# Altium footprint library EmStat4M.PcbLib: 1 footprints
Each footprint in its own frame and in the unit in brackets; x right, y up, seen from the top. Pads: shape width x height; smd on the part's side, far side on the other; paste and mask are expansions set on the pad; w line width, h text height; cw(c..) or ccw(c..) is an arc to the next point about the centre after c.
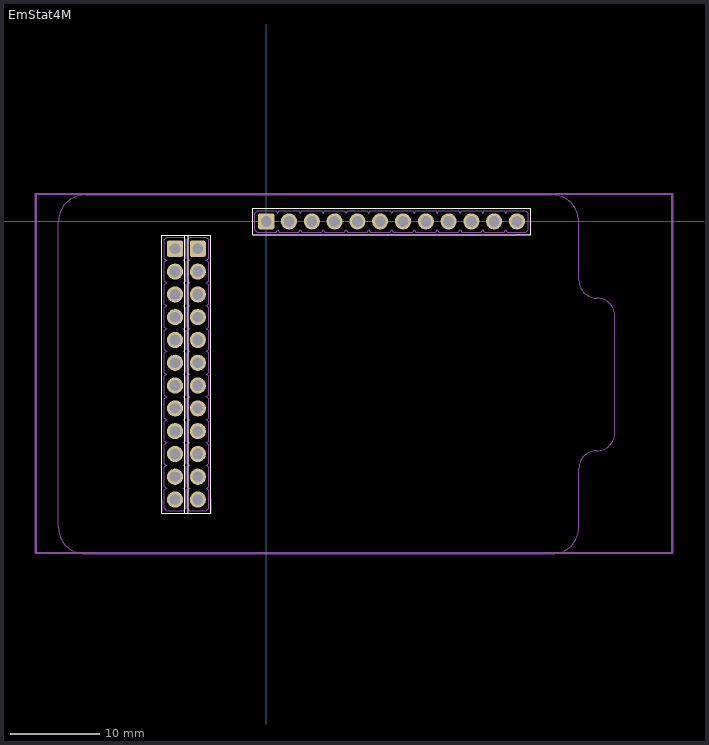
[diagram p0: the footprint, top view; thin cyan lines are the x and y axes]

## EmStat4M [mm] "EmStat 4 Module"
pads (36):
  rrect25% 1.8x1.8 hole 1.2: Con1-1(0,0) Con2-1(-10.16,-3.048) Con3-1(-7.62,-3.048)
  round 1.8 hole 1.2: Con1-2(2.54,0) Con1-3(5.08,0) Con1-4(7.62,0) Con1-5(10.16,0) Con1-6(12.7,0) Con1-7(15.24,0) Con1-8(17.78,0) Con1-9(20.32,0) Con1-10(22.86,0) Con1-11(25.4,0) Con1-12(27.94,0) Con2-2(-10.16,-5.588) Con2-3(-10.16,-8.128) Con2-4(-10.16,-10.668) Con2-5(-10.16,-13.208) Con2-6(-10.16,-15.748) Con2-7(-10.16,-18.288) Con2-8(-10.16,-20.828) Con2-9(-10.16,-23.368) Con2-10(-10.16,-25.908) Con2-11(-10.16,-28.448) Con2-12(-10.16,-30.988) Con3-2(-7.62,-5.588) Con3-3(-7.62,-8.128) Con3-4(-7.62,-10.668) Con3-5(-7.62,-13.208) Con3-6(-7.62,-15.748) Con3-7(-7.62,-18.288) Con3-8(-7.62,-20.828) Con3-9(-7.62,-23.368) Con3-10(-7.62,-25.908) Con3-11(-7.62,-28.448) Con3-12(-7.62,-30.988)
Top Overlay:
  lines w0.1: -11.62,-1.528 -11.62,-3.057 -11.62,-30.997 -11.62,-32.508 -10.15,-32.508 -8.708,-32.508 ; -11.612,-1.528 -10.17,-1.528 -8.7,-1.528 -8.7,-3.039 -8.7,-30.979 -8.7,-32.508 ; -9.08,-1.528 -9.08,-3.057 -9.08,-30.997 -9.08,-32.508 -7.61,-32.508 -6.168,-32.508 ; -9.072,-1.528 -7.63,-1.528 -6.16,-1.528 -6.16,-3.039 -6.16,-30.979 -6.16,-32.508 ; -1.52,-1.46 0.009,-1.46 27.949,-1.46 29.46,-1.46 29.46,0.01 29.46,1.452 ; -1.52,-1.452 -1.52,-0.01 -1.52,1.46 -0.009,1.46 27.931,1.46 29.46,1.46
Mechanical 1:
  lines w0.1: -23.16,-34.048 ccw(c-20.16,-34.048) -20.16,-37.048 31.84,-37.048 ccw(c31.84,-34.048) 34.84,-34.048 34.84,-27.548 cw(c36.84,-27.548) 36.84,-25.548 ccw(c36.84,-23.548) 38.84,-23.548 38.84,-17.048 38.84,-10.548 ccw(c36.84,-10.548) 36.84,-8.548 cw(c36.84,-6.548) 34.84,-6.548 34.84,-0.048 ccw(c31.84,-0.048) 31.84,2.952 -20.16,2.952 ccw(c-20.16,-0.048) -23.16,-0.048 -23.16,-34.048
Mechanical 6:
  lines w0.1: -11.628,-30.997 -11.628,-3.057 -11.628,-1.528 ; -11.62,-1.528 -10.178,-1.528 -8.708,-1.528 -8.708,-3.039 -8.708,-30.918 ; -11.612,-30.997 -11.612,-32.508 -10.142,-32.508 -8.7,-32.508 ; -9.088,-30.997 -9.088,-3.057 -9.088,-1.528 ; -9.08,-1.528 -7.638,-1.528 -6.168,-1.528 -6.168,-3.039 -6.168,-30.918 ; -9.072,-30.997 -9.072,-32.508 -7.602,-32.508 -6.16,-32.508 ; -8.692,-32.508 -8.692,-30.979 ; -6.152,-32.508 -6.152,-30.979 ; -1.52,-1.468 0.009,-1.468 27.949,-1.468 ; -1.52,-1.46 -1.52,-0.018 -1.52,1.452 -0.009,1.452 27.87,1.452 ; 27.931,1.468 29.46,1.468 ; 27.949,-1.452 29.46,-1.452 29.46,0.018 29.46,1.46
Mechanical 8:
  drawing of 226 lines, arcs and shapes, not listed
3D body "68000-x02.stp": height 8.18, standoff -2.62, extent -1.27,-1.206 3.81,1.207
3D body "68000-x02.stp": height 8.18, standoff -2.62, extent 3.81,-1.206 8.89,1.207
3D body "68000-x02.stp": height 8.18, standoff -2.62, extent 8.89,-1.206 13.97,1.207
3D body "68000-x02.stp": height 8.18, standoff -2.62, extent 13.97,-1.206 19.05,1.207
3D body "68000-x02.stp": height 8.18, standoff -2.62, extent 19.05,-1.206 24.13,1.207
3D body "68000-x02.stp": height 8.18, standoff -2.62, extent 24.13,-1.206 29.21,1.207
3D body "68000-x02.stp": height 8.18, standoff -2.62, extent -11.366,-32.258 -8.953,-27.178
3D body "68000-x02.stp": height 8.18, standoff -2.62, extent -11.366,-27.178 -8.953,-22.098
3D body "68000-x02.stp": height 8.18, standoff -2.62, extent -11.366,-22.098 -8.953,-17.018
3D body "68000-x02.stp": height 8.18, standoff -2.62, extent -11.366,-17.018 -8.953,-11.938
3D body "68000-x02.stp": height 8.18, standoff -2.62, extent -11.366,-11.938 -8.953,-6.858
3D body "68000-x02.stp": height 8.18, standoff -2.62, extent -11.366,-6.858 -8.953,-1.778
3D body "68000-x02.stp": height 8.18, standoff -2.62, extent -8.826,-32.258 -6.413,-27.178
3D body "68000-x02.stp": height 8.18, standoff -2.62, extent -8.826,-27.178 -6.413,-22.098
3D body "68000-x02.stp": height 8.18, standoff -2.62, extent -8.826,-22.098 -6.413,-17.018
3D body "68000-x02.stp": height 8.18, standoff -2.62, extent -8.826,-17.018 -6.413,-11.938
3D body "68000-x02.stp": height 8.18, standoff -2.62, extent -8.826,-11.938 -6.413,-6.858
3D body "68000-x02.stp": height 8.18, standoff -2.62, extent -8.826,-6.858 -6.413,-1.778
3D body "EmStat 4S.step": height 16.86, standoff -1.12, extent -25.674,-36.952 45.232,3.048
